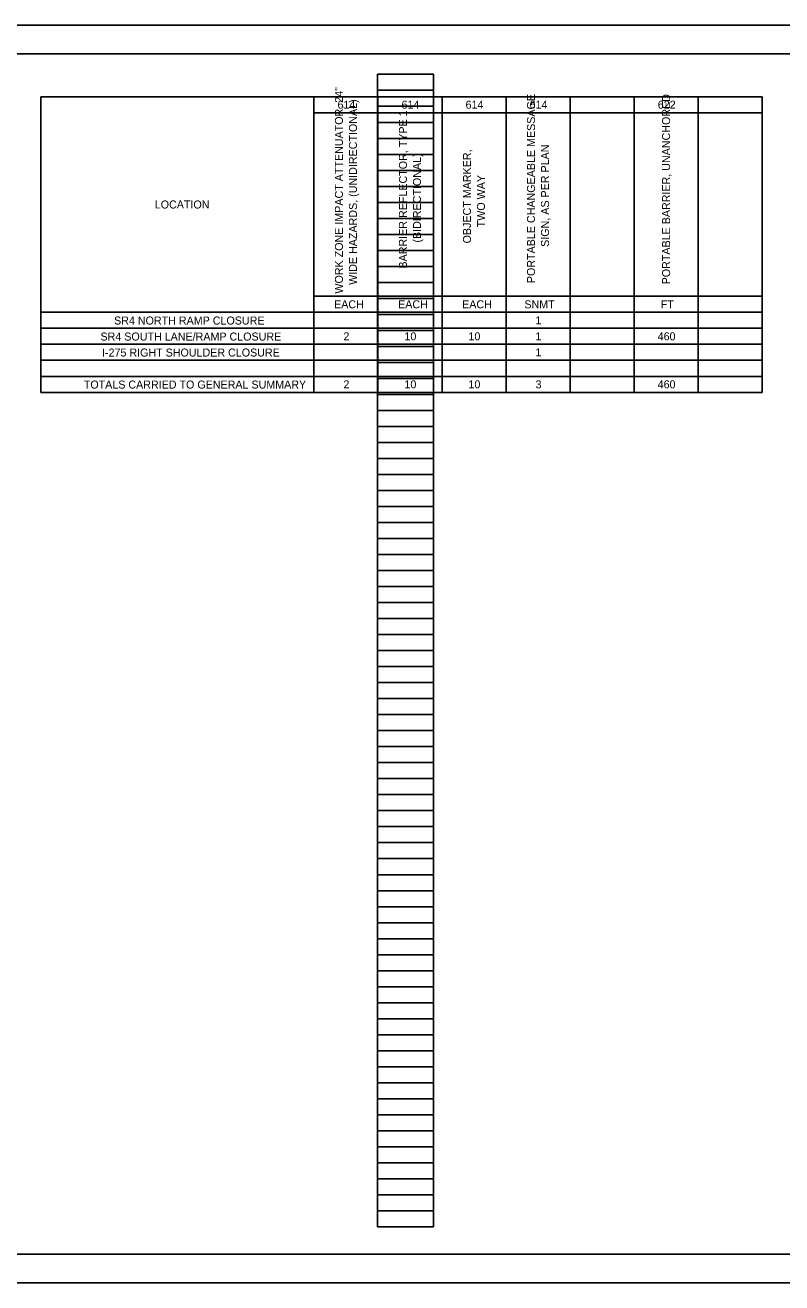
# Model space of a CAD drawing. Extents: x 0 to 50.1, y 0 to 22.
# Drawn here: x 17.52 to 30.75, y 0 to 22 of the extents above; entities that cross this region are included whole.
import ezdxf

# ---------------------------------------------------------------- set-up
doc = ezdxf.new("R2010")
doc.units = 0
for name, color, linetype in [('Default', 7, 'Continuous'), ('SH_Border', 7, 'Continuous'), ('SH_Cut_Line', 7, 'Continuous'), ('SH_Data', 7, 'Continuous')]:
    doc.layers.add(name, color=color, linetype=linetype)

msp = doc.modelspace()

# ---------------------------------------------------------------- linework, layer by layer
at = {"layer": 'Default'}
for p, q in [((17.793, 20.749), (30.409, 20.749)), ((17.793, 20.749), (17.793, 15.577)), ((22.569, 20.749), (22.569, 15.577)), ((23.689, 20.749), (23.689, 15.577)), ((24.809, 20.749), (24.809, 15.577)), ((25.929, 20.749), (25.929, 15.577)), ((27.049, 20.749), (27.049, 15.577)), ((28.169, 20.749), (28.169, 15.577)), ((29.289, 20.749), (29.289, 15.577)), ((30.409, 20.749), (30.409, 15.577)), ((22.569, 20.469), (30.409, 20.469)), ((22.569, 17.257), (30.409, 17.257)), ((17.793, 16.977), (30.409, 16.977)), ((17.793, 16.697), (30.409, 16.697)), ((17.793, 16.417), (30.409, 16.417)), ((17.793, 16.137), (30.409, 16.137)), ((17.793, 15.857), (30.409, 15.857)), ((17.793, 15.577), (30.409, 15.577))]:
    msp.add_line(p, q, dxfattribs=at)
at = {"layer": 'SH_Border'}
msp.add_lwpolyline([(1.5, 21.5), (33.5, 21.5), (33.5, 0.5), (1.5, 0.5)], close=True, dxfattribs=at)
at = {"layer": 'SH_Cut_Line'}
msp.add_lwpolyline([(0, 0), (34, 0), (34, 22), (0, 22)], close=True, dxfattribs=at)
at = {"layer": 'SH_Data'}
for p, q in [((23.68, 0.98), (23.68, 21.14)), ((23.68, 21.14), (24.66, 21.14)), ((24.66, 0.98), (24.66, 21.14)), ((23.68, 20.86), (24.66, 20.86)), ((23.68, 20.58), (24.66, 20.58)), ((23.68, 20.3), (24.66, 20.3)), ((23.68, 20.02), (24.66, 20.02)), ((23.68, 19.74), (24.66, 19.74)), ((23.68, 19.46), (24.66, 19.46)), ((23.68, 19.18), (24.66, 19.18)), ((23.68, 18.9), (24.66, 18.9)), ((23.68, 18.62), (24.66, 18.62)), ((23.68, 18.34), (24.66, 18.34)), ((23.68, 18.06), (24.66, 18.06)), ((23.68, 17.78), (24.66, 17.78)), ((23.68, 17.5), (24.66, 17.5)), ((23.68, 17.22), (24.66, 17.22)), ((23.68, 16.94), (24.66, 16.94)), ((23.68, 16.66), (24.66, 16.66)), ((23.68, 16.38), (24.66, 16.38)), ((23.68, 16.1), (24.66, 16.1)), ((23.68, 15.82), (24.66, 15.82)), ((23.68, 15.54), (24.66, 15.54)), ((23.68, 15.26), (24.66, 15.26)), ((23.68, 14.98), (24.66, 14.98)), ((23.68, 14.7), (24.66, 14.7)), ((23.68, 14.42), (24.66, 14.42)), ((23.68, 14.14), (24.66, 14.14)), ((23.68, 13.86), (24.66, 13.86)), ((23.68, 13.58), (24.66, 13.58)), ((23.68, 13.3), (24.66, 13.3)), ((23.68, 13.02), (24.66, 13.02)), ((23.68, 12.74), (24.66, 12.74)), ((23.68, 12.46), (24.66, 12.46)), ((23.68, 12.18), (24.66, 12.18)), ((23.68, 11.9), (24.66, 11.9)), ((23.68, 11.62), (24.66, 11.62)), ((23.68, 11.34), (24.66, 11.34)), ((23.68, 11.06), (24.66, 11.06)), ((23.68, 10.78), (24.66, 10.78)), ((23.68, 10.5), (24.66, 10.5)), ((23.68, 10.22), (24.66, 10.22)), ((23.68, 9.94), (24.66, 9.94)), ((23.68, 9.66), (24.66, 9.66)), ((23.68, 9.38), (24.66, 9.38)), ((23.68, 9.1), (24.66, 9.1)), ((23.68, 8.82), (24.66, 8.82)), ((23.68, 8.54), (24.66, 8.54)), ((23.68, 8.26), (24.66, 8.26)), ((23.68, 7.98), (24.66, 7.98)), ((23.68, 7.7), (24.66, 7.7)), ((23.68, 7.42), (24.66, 7.42)), ((23.68, 7.14), (24.66, 7.14)), ((23.68, 6.86), (24.66, 6.86)), ((23.68, 6.58), (24.66, 6.58)), ((23.68, 6.3), (24.66, 6.3)), ((23.68, 6.02), (24.66, 6.02)), ((23.68, 5.74), (24.66, 5.74)), ((23.68, 5.46), (24.66, 5.46)), ((23.68, 5.18), (24.66, 5.18)), ((23.68, 4.9), (24.66, 4.9)), ((23.68, 4.62), (24.66, 4.62)), ((23.68, 4.34), (24.66, 4.34)), ((23.68, 4.06), (24.66, 4.06)), ((23.68, 3.78), (24.66, 3.78)), ((23.68, 3.5), (24.66, 3.5)), ((23.68, 3.22), (24.66, 3.22)), ((23.68, 2.94), (24.66, 2.94)), ((23.68, 2.66), (24.66, 2.66)), ((23.68, 2.38), (24.66, 2.38)), ((23.68, 2.1), (24.66, 2.1)), ((23.68, 1.82), (24.66, 1.82)), ((23.68, 1.54), (24.66, 1.54)), ((23.68, 1.26), (24.66, 1.26)), ((23.68, 0.98), (24.66, 0.98))]:
    msp.add_line(p, q, dxfattribs=at)

# ---------------------------------------------------------------- texts
at = {"layer": 'Default'}
for s, p in [('WORK ZONE IMPACT ATTENUATOR, 24" ', (23.076, 17.304)), ('WIDE HAZARDS, (UNIDIRECTIONAL)', (23.321, 17.457)), ('PORTABLE CHANGEABLE MESSAGE ', (26.436, 17.487)), ('PORTABLE BARRIER, UNANCHORED', (28.799, 17.466)), ('BARRIER REFLECTOR, TYPE 1 ', (24.196, 17.742)), ('OBJECT MARKER, ', (25.316, 18.182)), ('SIGN, AS PER PLAN', (26.681, 18.122)), ('(BIDIRECTIONAL)', (24.441, 18.197)), ('TWO WAY', (25.561, 18.464))]:
    msp.add_text(s, height=0.14, rotation=90, dxfattribs=at).set_placement(p)
for s, p in [('614', (22.981, 20.539)), ('614', (24.101, 20.539)), ('614', (25.221, 20.539)), ('614', (26.341, 20.539)), ('622', (28.584, 20.539)), ('LOCATION', (19.784, 18.793)), ('EACH', (22.921, 17.047)), ('EACH', (24.041, 17.047)), ('EACH', (25.161, 17.047)), ('SNMT', (26.25, 17.047)), ('FT', (28.636, 17.047)), ('SR4 NORTH RAMP CLOSURE', (19.072, 16.763)), ('1', (26.444, 16.767)), ('SR4 SOUTH LANE/RAMP CLOSURE', (18.834, 16.483)), ('2', (23.085, 16.487)), ('10', (24.152, 16.487)), ('10', (25.272, 16.487)), ('1', (26.444, 16.487)), ('460', (28.582, 16.487)), ('I-275 RIGHT SHOULDER CLOSURE', (18.861, 16.203)), ('1', (26.444, 16.207)), ('TOTALS CARRIED TO GENERAL SUMMARY', (18.542, 15.643)), ('2', (23.085, 15.647)), ('10', (24.152, 15.647)), ('10', (25.272, 15.647)), ('3', (26.446, 15.647)), ('460', (28.582, 15.647))]:
    msp.add_text(s, height=0.14, dxfattribs=at).set_placement(p)

doc.saveas('drawing.dxf')
